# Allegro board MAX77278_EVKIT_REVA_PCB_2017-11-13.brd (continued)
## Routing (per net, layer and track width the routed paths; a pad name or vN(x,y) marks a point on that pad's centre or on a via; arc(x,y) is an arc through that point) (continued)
VBATT: length 3.9
  TOP w0.254: 51.13,39.42 v2(51.21,39.34) 51.08,39.22 C7.2 51,39.19 50.9,39.29 50.9,39.34 v2(50.9,39.34) ; 51.11,39.44 U1.E3
  TOP w0.381: v1(52.6,6.91) 52.62,6.91 ; 52,7.26 v1(52,7.55) C15.1 52.69,7.5 ; v1(52.02,6.99) 52.02,7.1
  INTERNAL2 w0.254: v2(50.9,39.34) 50.95,39.34 51.01,39.29 51.02,39.29 51.05,39.26 51.05,39.2 50.92,39.08 v2(50.9,39.08) 50.91,39.07 50.92,39.07 50.63,39.01 v3(50.58,38.97)
  vias: v2(51.23,39.09) v3(50.39,38.56)
AMUX: length 152.7
  TOP w0.127: v1(20.4,41.63) 20.94,41.63 21.15,41.43 23.34,41.43 23.65,41.73 49.35,41.73 49.63,41.45 U1.C1
  TOP w0.254: v1(83.6,71.05) v1(88.12,71.05)
  INTERNAL3 w0.254: v4(21.4,70.58) 21.4,65.75 20.39,64.73 20.39,42.32 20.4,42.32 v1(20.4,41.63) ; AMUX.1 v4(50.16,70.56) ; J2.2 v4(77.72,71.02)
  BOTTOM w0.254: R285.1 88.21,71.14 v1(88.12,71.05) ; v4(21.4,70.58) 50.04,70.58 ; 50.04,70.58 66.83,70.58 67.09,70.84 76.94,70.84 77.11,71.02 v4(77.72,71.02) 77.97,71.02 78,71.05 v1(83.6,71.05) ; 50.04,70.58 50.05,70.56 v4(50.16,70.56)
BST: length 5.2
  TOP w0.254: C4.1 55.68,38.33 55.68,38.76 v1(55.6,38.84)
  INTERNAL2 w0.254: v2(52.31,41.45) 52.89,41.45 53.04,41.3 v3(53.08,41.3)
  INTERNAL3 w0.254: v3(53.08,41.3) v4(53.55,41.3)
  BOTTOM w0.254: v4(53.55,41.3) 55.17,39.68 55.17,39.27 v1(55.6,38.84)
CHGIN: length 8
  TOP w0.254: U1.E1 49.62,40.65 49.48,40.51 v2(49.43,40.51) ; J1.1 43.59,5.35 43.62,5.38
  TOP w0.381: 43.62,5.38 43.62,8
  TOP w1.27: CHGIN.1 42.76,8.86 43.62,8
  INTERNAL2 w0.254: 49.3,40.08 49.5,40.28 49.5,40.44 v2(49.43,40.51) v2(49.73,40.51) ; 49.27,40.05 49.17,40.05 v3(49.15,40.03)
  vias: v2(48.92,40.34) v2(49.12,40.51) v3(48.72,39.98)
CS: length 57.5
  TOP w0.254: R9.2 52.53,43.48 51.91,42.87 U1.A5
  TOP w0.508: R9.2 53.29,44.46 53.85,45.02 53.85,47.17 v1(54.33,47.65) ; CS.1 v1(58.12,77.6)
  INTERNAL3 w0.508: 58.06,77.77 58.12,77.72 v1(58.12,77.6)
  INTERNAL3 w0.762: v1(54.33,47.65) 58.06,51.38 58.06,94.01 58.04,94.03 J5.2
CTSN: length 20.4
  TOP w0.254: U100.39 22.68,88.62 22.68,88.62 v1(23.34,88.62) ; v1(15.9,80.39) 15.9,79 16.56,78.34 U101.8
  INTERNAL3 w0.254: v1(23.34,80.48) v1(23.34,88.62)
  BOTTOM w0.254: v1(15.9,80.39) 22.64,80.39 22.73,80.48 v1(23.34,80.48)
DCDN: length 7.5
  TOP w0.254: v1(16.64,79.28) 16.64,78.99 17.06,78.57 U101.7 ; v1(17.9,79.28) 18.33,79.71 18.33,79.73 19.53,80.93 U100.25
  BOTTOM w0.254: v1(16.64,79.28) v1(17.9,79.28)
DSRN: length 6.2
  TOP w0.254: U101.6 17.56,78.82 17.33,79.04 17.33,79.44 19.03,81.13 U100.24
DTRN: length 8.2
  TOP w0.254: U101.31 21.87,76.21 v1(22.02,76.35) ; U100.28 21.08,82.82 v1(21.08,81.94)
  INTERNAL3 w0.254: v1(22.02,76.35) 22.02,80.82 21.08,81.76 v1(21.08,81.94)
GPIO0: length 74.2
  TOP w0.127: v1(17.86,43.99) 18.29,43.99 19.08,43.21 49.47,43.21 50.01,42.66 50.01,42.22 50.01,42.21 50.01,41.99 50.15,41.85 U1.B1
  TOP w0.254: R21.2 25.08,63.86 24.93,63.7 GPIO0.1 22.57,63.7 22.54,63.73 v1(19.38,63.73) ; v1(17.86,43.99) 11.38,43.99 8.31,47.07 7.8,47.07 7.8,47.07 SW0.4
  INTERNAL3 w0.152: v1(17.86,43.99) 17.86,57.35 19.33,58.83 19.33,63.12 19.38,63.17 v1(19.38,63.73)
GPIO1: length 58
  TOP w0.127: v1(21.06,59.26) 22.78,59.26 22.81,59.28 23.93,59.28 ; v2(49.74,42.27) 49.71,42.29 49.59,42.29 49.21,42.67 21.31,42.67 v1(21.06,42.42)
  TOP w0.254: 23.93,59.28 GPIO1.1 25.11,59.28 25.16,59.23 R19.2 ; SW1.4 v1(21.08,47.07)
  INTERNAL2 w0.102: v2(50.7,41.88) 50.32,42.27 v2(49.74,42.27)
  INTERNAL3 w0.127: v1(21.06,42.42) v1(21.06,59.26)
  INTERNAL3 w0.254: v1(21.08,47.07) 21.06,47.09
GPIO2: length 71.4
  TOP w0.127: v2(49.71,42.57) 49.34,42.94 19.08,42.94 18.99,42.85 v1(18.44,42.85)
  TOP w0.152: v1(18.44,54.53) 19,54.53 19.02,54.56 22.77,54.56 22.8,54.58 23.93,54.58
  TOP w0.254: SW2.4 7.88,34.78 10.97,37.87 v1(18.44,37.87) ; R16.2 25.16,54.64 25.11,54.58 GPIO2.1 23.93,54.58
  INTERNAL2 w0.102: v2(51.09,41.88) 50.39,42.57 v2(49.71,42.57)
  INTERNAL3 w0.127: v1(18.44,54.53) v1(18.44,42.85)
  INTERNAL3 w0.152: v1(18.44,42.85) v1(18.44,37.87)
GPIO3: length 54.8
  TOP w0.127: v1(22.5,41.83) 23.05,41.83 23.25,42.03 49.49,42.03 v2(49.79,41.74)
  TOP w0.152: v1(22.1,34.9) 21.54,34.9 21.42,34.78 SW3.4
  TOP w0.254: 25.29,50.06 26.47,50.06 26.52,50.11 ; 25.29,50.06 GPIO3.1 ; 25.29,50.06 25.34,50.11 26.52,50.11 ; 26.52,50.11 R6.2
  INTERNAL2 w0.102: v2(49.79,41.74) 50.09,41.43 50.22,41.43 50.22,41.43 v2(50.69,41.43)
  INTERNAL3 w0.152: 24.1,50.06 22.5,48.46 v1(22.5,41.83) 22.5,41.27 22.1,40.87 v1(22.1,34.9)
  INTERNAL3 w0.254: GPIO3.1 24.1,50.06
GPIO4: length 69.8
  TOP w0.127: SW4.4 7.81,22.84 7.84,22.86 8.1,22.86 11.51,26.26 v1(20.5,26.26) ; v1(45.77,41.15) 25.06,41.15 24.78,40.87 v1(24.23,40.87) 23.69,40.87 23.51,41.05 21.22,41.05 21.04,40.87 v1(20.5,40.87)
  TOP w0.254: R8.1 25.44,45.42 25.39,45.36 GPIO4.1
  INTERNAL2 w0.102: v2(51.51,41.05) 51.05,40.59 51.03,40.59 v3(50.67,40.23)
  INTERNAL3 w0.102: v3(50.67,40.23) 50.67,40.87 49.82,41.72 46.34,41.72 v1(45.77,41.15)
  INTERNAL3 w0.127: v1(20.5,40.87) v1(20.5,26.26)
  INTERNAL3 w0.254: GPIO4.1 24.51,43.92 24.23,43.64 v1(24.23,40.87)
GPIO5: length 60.2
  TOP w0.127: 24.49,37.64 v1(21.51,37.64) ; v2(49.12,42.34) 22.42,42.34 22.21,42.14 v1(21.67,42.14)
  TOP w0.152: v1(21.51,22.86) 20.96,22.86 20.93,22.84 SW5.4
  TOP w0.381: 24.49,37.64 GPIO5.1 25.73,37.64 25.76,37.67 R18.1
  INTERNAL2 w0.076: v2(51.11,41.45) 51.1,41.45 50.9,41.66 50.5,41.66
  INTERNAL2 w0.127: v2(49.12,42.34) 49.42,42.05 49.6,42.05 49.66,41.99 49.99,41.99 50.32,41.66 50.5,41.66
  INTERNAL3 w0.127: v1(21.51,22.86) v1(21.51,37.64) 21.51,41.44 21.67,41.59 v1(21.67,42.14)
GPIO6: length 86.1
  TOP w0.127: v2(49.96,43.1) 49.59,43.47 19.91,43.47 19.65,43.74 v1(19.1,43.74)
  TOP w0.152: v1(18.92,13.34) 9.17,13.34 7,11.16 SW6.4 ; 24.41,33.05 v1(19.1,33.05)
  TOP w0.381: R20.1 25.68,33.02 25.65,33.05 GPIO6.1 24.41,33.05
  INTERNAL2 w0.076: v2(51.49,41.48) 51.49,41.53 51.31,41.71 51.31,42.01 50.98,42.34
  INTERNAL2 w0.102: 50.98,42.34 50.5,42.82 50.25,42.82 v2(49.96,43.1)
  INTERNAL3 w0.127: v1(19.1,43.74) v1(19.1,33.05)
  INTERNAL3 w0.152: v1(18.92,13.34) 18.92,32.31 19.1,32.49 v1(19.1,33.05)
GPIO7: length 97.1
  TOP w0.152: 24.41,27.76 23.28,27.76 23.25,27.79 v1(19.74,27.79) ; SW7.4 v1(19.73,10.09)
  TOP w0.381: R22.1 25.81,27.91 25.65,27.76 GPIO7.1 24.41,27.76
  INTERNAL2 w0.076: v2(51.54,41.88) 51.85,42.19 51.85,42.63
  INTERNAL2 w0.102: v3(51.92,43.21) 51.92,42.7 51.85,42.63
  INTERNAL3 w0.127: v3(51.92,43.21) 51.92,44.22 51.13,45.01 51.13,52.86 v1(50.95,53.04)
  INTERNAL3 w0.152: v1(19.73,10.09) 19.73,10.13 19.74,10.13 v1(19.74,27.79) 19.74,44.73 19.61,44.86 v1(19.61,53.04)
  BOTTOM w0.152: v1(50.95,53.04) v1(19.61,53.04)
GROUND: length 133.9
  TOP w0.152: v1(83.05,8.62) 82.8,8.37 U206.A3 ; C224.2 v1(83.83,6.29)
  TOP w0.203: U1.E4 51.51,40.39 v2(51.51,40.39)
  TOP w0.254: C159.2 21.23,78.91 v1(20.88,78.56) ; C158.1 v1(33.14,90.21) 33.15,90.22 33.46,89.9 R159.2 ; v1(18.36,81.92) 18.36,81.72 C150.2 18.09,81.43 18.53,81.87 U100.23 ; R166.2 v1(55.52,82.27) ; U101.26 21.56,73.71 v1(21.69,73.58) ; U103.2 38.21,86.19 38.44,85.96 C110.1 v1(39.31,85.2) ; Y101.4 v1(27.95,94.12) ; U100.1 12.88,90.12 v1(12.34,90.65) ; v1(28.22,76.94) 28.56,77.28 U107.5 U107.13 ; Q100.2 36.09,45.67 R138.2 ; 44.86,85.67 45.08,85.45 C112.1 ; C15.2 54.09,7.55 54.38,7.85 v1(54.86,7.85) ; U101.20 18.06,71.67 v1(17.83,71.45) ; 9.5,70.1 9.26,69.87 R115.2 ; 9.5,70.1 C154.1 ; 9.5,70.1 9.9,70.1 9.9,70.19 v1(9.99,70.28) ; U100.35 23.69,86.62 v1(23.95,86.36) ; U100.3 12.79,89.12 v1(12.42,88.75) 12.55,88.62 U100.4 ; U1.E6 52.31,40.37 ; R157.2 45.33,90.38 C113.1 ; v1(27.03,84.8) C120.1 27.04,84.2 27.85,84.2 27.86,84.21 C115.1 ; v1(33.32,85.26) 32.73,85.26 C118.1 32.51,85.13 32.51,85.51 32.27,85.75 U102.2 ; U101.17 16.44,72.33 v1(15.56,72.33) 15.51,72.28 C156.1 14.35,72.3 C155.2 ; R13.2 v1(24.86,7.13) ; v1(18.06,78.56) 18.56,78.06 U101.4 ; Y101.2 23.7,91.92 C152.1 23.55,91.02 v1(23.93,90.64) 24.22,90.35 C153.1 ; C6.1 54.81,40.11 54.81,39.73 ; C134.1 41.63,48.29 v1(41.49,48.15) 41.37,48.02 Q101.2 40.68,47.11 40.79,47.01 R137.2 ; U101.24 20.19,72.33 v1(20.46,72.33) ; R161.2 39.76,89.99 v1(39.32,90.42) 39.27,90.38 C111.1 ; v1(64.11,83.2) 63.55,83.76 R7.2 62.84,83.84 Q1.2 ; U104.2 44.79,85.83 ; v1(26.52,89.28) 26.42,89.18 26.16,89.18 25.87,88.89 C151.2 ; RT1.2 v1(29.26,6.05) ; v2(51.51,42.25) 51.51,43.23 ; C108.1 v1(15.63,70.73) ; v1(37.11,47.19) 37.06,47.24 C129.1
  TOP w0.381: C5.1 54.81,43.36 54.81,43.29 ; C5.1 54.91,43.44 55,43.53 v1(55.26,43.53) ; C5.1 55.29,43.84 C36.1 55.52,44.48 C37.1 ; Q100.2 36.84,46.93 v1(37.11,47.19) ; U108.2 49.6,81.41 v1(48.46,81.41) ; C12.1 48.37,43.94 v1(47.79,43.94) ; C241.1 89.37,33.56 ; 31.25,91.85 31.2,91.9 v1(30.66,91.9) ; J6.5 5.49,75.82 5.49,75.82 6.89,75.82 6.9,75.82 v1(7.57,75.82) ; C242.1 89.84,62.02 ; C113.1 44.58,90.01 v1(44.78,89.81) ; C239.1 v1(90.04,49.28) ; v2(54.98,41.68) 54.89,41.77 C9.1 54.88,41.82 C8.1 ; v1(27.54,89.89) R110.2
  TOP w0.457: v1(41.05,6.81) 41.05,5.34 J1.5
  TOP w0.508: R23.2 v1(21.87,19.58) ; SW9.3 v1(1.2,57.88)
  INTERNAL2 w0.254: v2(51.51,40.39) 50.88,39.75 50.35,39.75
  BOTTOM w0.127: R233.2 90.16,42.33 90.08,42.42 89.5,42.42 88.38,41.29 84.87,41.29 84.13,42.03 R230.2 ; 90.43,34.98 90.43,35.39 90.3,35.51 89.87,35.51 88.39,34.04 85.09,34.04 84.61,34.52 83.72,34.52 R243.2 ; R255.2 88.3,62.7 89.08,63.47 89.99,63.47 90.03,63.43 90.05,63.43 R258.2 ; R211.2 90.18,50.62 90.11,50.69 89.47,50.69 87.92,49.14 R208.2
  BOTTOM w0.254: U209.15 88.95,82.26 89.56,82.87 R282.2 89.56,83.93 ; C222.1 v1(64.45,73.42) ; v1(92.86,54.25) 92.86,53.95 R210.1 ; 89.56,83.93 C238.1 ; 89.56,83.93 89.63,83.86 C237.1 v1(91.45,83.86) ; C249.1 v4(89.54,72.82) ; v1(62.74,79.96) R308.1 63.48,79.93 R307.1 ; U205.4 68.65,73.48 68.31,73.13 v1(68.31,72.83) ; v4(83.63,71.97) 84.25,71.97 C228.1 ; C223.1 v1(71.24,71.97) ; R257.1 v1(96.01,67.03)
  BOTTOM w0.381: C251.1 65.63,65.56 65.67,65.59 65.67,65.92 v1(65.68,65.94) ; v1(99.72,73.61) 99.65,73.54 99.24,73.54 U210.2 ; R211.2 90.04,49.88 v1(90.04,49.28) ; C244.1 90.92,76.59 v1(90.95,76.62) ; U207.2 85.26,13.46 85.56,13.75 R268.2 86.78,13.75 C227.2 86.8,14.83 C236.1 v1(86.99,15.64) ; 98.13,38.85 97.76,38.48 R244.1 ; C226.2 v1(81.85,16.14) ; R287.2 98.81,78.91 98.81,78.24 v1(98.75,78.18) ; R231.1 96.03,42.55 v1(96.07,42.51) ; C235.1 93.52,73.57 C234.1 92.78,73.56 v1(92.33,74.02) ; v1(66.27,29.84) 66.26,29.84
  BOTTOM w0.508: Q206.2 v1(98.75,78.18)
  vias: v1(7.29,65.3) v1(7.98,82.91) v1(9.8,69.6) v1(10.29,77.47) v1(12.55,94.18) v1(13.36,1.83) v1(18.34,1.93) v1(19.18,48.06) v1(20.32,25.6) v1(21.29,94.59) v1(31.45,1.93) v1(32.97,9.02) v1(32.97,8.46) v1(33.49,9) v1(33.53,8.46) v1(40.34,7.52) v1(40.34,6.81) v1(41.05,7.52) v1(43.28,60.11) v1(43.28,59.51) v1(43.28,58.89) v1(43.34,56.76) v1(43.34,56.16) v1(43.37,55.52) v1(43.9,60.14) v1(43.9,59.49) v1(43.88,58.89) v1(43.95,56.78) v1(43.96,56.14) v1(43.94,55.54) v1(44.04,49.81) v1(44.07,49.17) v1(45.69,35.37) v1(45.71,34.73) v1(46.29,35.36) v1(46.29,34.72) v1(48.21,89.18) v1(49.15,46.53) v1(49.8,37.21) v1(50.29,46) v1(50.39,37.22) v1(51.36,2.24) v1(54.86,7.32) v1(55.52,7.85) v1(55.52,7.32) v1(55.73,44.04) v1(57.35,2.24) v1(59.22,14.31) v1(59.22,13.67) v1(61.74,8.16) v1(62.97,8.16) v1(63.4,42.11) v1(65.63,49.94) v1(65.61,40.64) v1(66.23,14.79) v1(66.18,8.27) v1(66.28,13.67) v1(67.46,14.79) v1(67.41,8.27) v1(67.53,13.68) v1(68.5,66.52) v1(68.5,50.47) v1(69.29,40.74) v1(69.44,2.24) v1(69.67,13.56) v1(69.66,11.87) v1(69.75,34.44) v1(69.93,29.03) v1(69.95,26.39) v1(70.05,50.8) v1(70.05,49.68) v1(70.79,13.55) v1(70.97,68.88) v1(70.89,11.87) v1(72.29,72.9) v1(73.08,44.4) v1(73.27,43.22) v1(73.24,41.89) v1(73.56,34.54) v1(73.66,60.55) v1(73.74,26.44) v1(74.22,75.59) v1(74.48,41.89) v1(74.5,43.22) v1(74.9,71.32) v1(75.13,82.07) v1(75.64,41.66) v1(76.15,41.05) v1(76.45,61.57) v1(76.45,60.86) v1(76.66,40.64) v1(76.66,33.17) v1(76.81,57.78) v1(76.8,57.21) v1(76.96,2.13) v1(77.27,60.86) v1(78.03,57.78) v1(78.03,57.21) v1(78.69,61.47) v1(78.82,33.5) v1(79.3,41.15) v1(79.5,61.47) v1(79.58,33.5) v1(79.71,49.28) v1(79.81,41.66) v1(79.96,35.69) v1(79.96,34.87) v1(79.96,34.11) v1(80.01,62.69) v1(80.01,61.98) v1(80.11,50.5) v1(80.11,49.78) v1(80.11,42.27) v1(81.27,74.24) v1(81.24,3.13) v1(81.24,2.57) v1(81.53,79.76) v1(82.02,3.13) v1(82.03,2.58) v1(84.07,84.18) v1(84.2,81.73) v1(85.5,70.41) v1(85.5,68.17) v1(86.31,61.26) v1(86.41,57.71) v1(86.41,53.75) v1(86.49,40.51) v1(86.74,19) v1(88.62,18.82) v1(88.86,20.84) v1(89.92,62.1) v1(90.1,20.84) v1(90.09,18.14) v1(90.55,9.55) v1(90.68,49.28) v1(90.8,63.12) v1(90.8,62.48) v1(90.8,49.91) v1(90.8,42.24) v1(90.8,41.63) v1(91.06,35.05) v1(91.06,34.42) v1(91.49,54.05) v1(91.9,67.16) v1(92.66,9.47) v1(97.69,58.72) v1(98.17,38.89) v1(98.58,76.48) v1(98.81,47.96) v1(98.81,38.91) v2(47.36,40.55) v2(47.35,40.25) v2(47.36,39.94) v2(47.66,40.24) v2(47.71,41.27) v2(47.68,40.54) v2(49.76,38.11) v2(49.75,37.8) v2(50.04,38.09) v2(50.04,37.81) v2(50.31,38.1) v2(50.32,37.8) v2(50.84,38.37) v2(50.84,38.07) v2(51.16,38.39) v2(51.16,38.09) v2(51.16,37.8) v2(51.47,38.39) v2(51.47,38.09) v2(53.88,39.66) v2(53.88,39.33) v2(53.87,39.03) v2(54.19,39.68) v2(54.2,39.33) v2(54.21,39.03) v2(54.5,39.68) v2(54.5,39.34) v2(54.81,39.69) v2(54.83,39.34) v2(54.98,41.96) v2(54.91,41.13) v2(54.91,40.79) v2(55.16,41.1) v2(55.16,40.77) v2(55.16,40.39) v2(55.16,40.06) v2(55.47,41.09) v2(55.47,40.77) v2(55.5,40.4) v2(55.51,40.06) v2(82.36,7.97)
IBATT: length 3.6
  BOTTOM w0.254: C228.2 85.14,71.98 R269.2 85.36,72.81 85.77,73.23 U209.7
IBATT_SNS: length 3.3
  TOP w0.127: U206.C1 81.92,7.53 v1(81.38,7.53)
  BOTTOM w0.127: R261.1 79.47,8.01 79.56,7.92 80.99,7.92 v1(81.38,7.53)
IBATT_SNS_RNG: length 135.2
  TOP w0.152: U206.A2 82.36,9.34 82.45,9.44 R284.2 v1(84.56,10.02)
  INTERNAL3 w0.152: v4(42.98,88.49) 42.98,90.5 40.56,92.91 J100.5 ; v1(84.56,5.52) v1(84.56,10.02) 84.56,11.14 81.37,14.34 81.37,72.86 81.91,73.41 v1(81.91,88.49)
  BOTTOM w0.152: v1(81.91,88.49) v4(42.98,88.49)
  BOTTOM w0.254: v1(84.56,5.52) 84.49,5.44 Q204.1
IN_SBB: length 6.1
  TOP w0.254: v1(61.09,13.94) 60.75,13.94 60.67,13.86 ; v2(52.14,39.32) 52.11,39.32 51.98,39.45 52.04,39.47 v2(52.13,39.63) ; v2(52.14,39.32) 52.14,39.32 52.1,39.32 51.91,39.48 51.88,39.48 ; v2(52.14,39.32) 52.14,39.33 52.12,39.33 ; C1.2 51.91,39.42 U1.E5
  INTERNAL2 w0.254: 52.11,39.35 52.06,39.31 v2(51.89,39.13) ; v2(52.14,39.32) 52.14,39.35 52.1,39.41 v2(52.13,39.63) ; v3(51.52,39.7) 51.56,39.69 51.57,39.66 51.57,39.43 51.87,39.13 v2(51.89,39.13) ; v2(51.89,39.13) 51.89,39.37 51.88,39.48
  INTERNAL3 w0.254: v4(51.92,39.39) 51.61,39.7 v3(51.52,39.7) 51.64,39.77 v3(51.82,40.01)
  BOTTOM w0.254: v4(51.92,39.39) 51.94,39.42 52.49,39.42 v4(52.47,39.39)
  vias: v1(60.73,12.83) v1(61.93,13.92) v1(61.9,12.83) v1(62.79,13.92) v1(62.81,12.83) v2(51.88,39.52)
INLDO: length 5.5
  TOP w0.254: 53.63,42.45 53.3,42.11 53.3,42.01 53.09,41.81 52.76,41.81 U1.B7
  TOP w0.381: R11.1 55.91,42.62 v1(56.22,42.93) ; 79.81,53.72 79.8,53.73 C18.2 ; 53.63,42.45 53.8,42.45 C13.1
  TOP w1.27: 83.32,53.69 INLDO.1
  INTERNAL2 w0.381: v2(53.89,42.64) 53.89,42.63 v3(54.23,42.63)
  INTERNAL3 w0.508: v1(56.22,42.93) 55.92,42.63 v3(54.23,42.63)
ISET_LDO: length 11.7
  INTERNAL3 w0.254: v1(64.49,72.67) v1(64.49,66.24)
  BOTTOM w0.254: v1(64.49,72.67) 66.37,72.67 67.35,73.65 U205.6 ; R250.1 64.49,65.54 v1(64.49,66.24)
ISET_SBB0: length 30.8
  INTERNAL3 w0.254: v4(64.71,49.98) 64.71,52.13 64.69,52.15 v4(64.69,52.89) ; v4(69.95,73.29) v4(69.95,52.89)
  BOTTOM w0.254: U205.2 v4(69.95,73.29) ; v4(69.95,52.89) v4(64.69,52.89) ; R203.1 v4(64.71,49.98)
ISET_SBB1: length 40.6
  INTERNAL3 w0.254: v4(64.74,42.55) v4(64.74,39.45) ; v4(69.3,72.55) v4(69.3,42.55)
  BOTTOM w0.254: v4(69.3,42.55) v4(64.74,42.55) ; v4(64.74,39.45) 64.74,38.83 R224.1 ; U205.3 v4(69.3,72.55)
ISET_SBB2: length 47
  INTERNAL3 w0.254: v4(67.57,73.11) v4(67.57,31.22)
  BOTTOM w0.254: v4(67.57,73.11) 68,73.54 U205.5 ; R237.1 64.63,30.72 65.13,31.22 v4(67.57,31.22)
LDO: length 3.7
  TOP w0.254: C5.2 53.9,43.44 53.24,42.77 53.13,42.77 52.71,42.35 U1.A7
  TOP w0.381: C37.2 54.39,44.81 C36.2 53.99,43.85 C5.2
  vias: v2(53.91,43.45)
LDO_DIV: length 13.8
  BOTTOM w0.254: U204.6 U204.7 76.14,79.02 76.35,78.82 86.06,78.82 86.39,79.15 86.39,79.41 86.41,79.43 U209.11
LXA: length 3.7
  TOP w0.254: v2(52.14,38.07) 52.17,38.09 52.29,38.09 ; v2(52.14,38.36) 52.29,38.21 52.29,38.09 ; 52.29,38.09 52.32,38.06 v2(52.42,38.06) ; 52.29,38.09 52.43,38.24 v2(52.43,38.36)
  INTERNAL2 w0.254: v2(51.91,41.05) 51.94,41.02 51.94,40.75 52.28,40.41
  INTERNAL2 w0.508: 52.66,38.6 52.66,40.03 52.28,40.41
LXB: length 3.8
  TOP w0.254: v2(53.43,38.05) 53.48,38.09 53.71,38.09 v2(53.76,38.04) ; v2(53.76,38.38) 53.63,38.25 53.63,38.18 v2(53.43,38.38)
  INTERNAL2 w0.254: v2(52.31,41.05) 52.52,41.05 52.88,40.69
  INTERNAL2 w0.508: 53.31,38.7 53.31,40.26 52.88,40.69
MAXQP03: length 1.8
  TOP w0.254: PO3.1 16.39,91.96 16.53,91.82 U100.52
MAXQP05: length 2
  TOP w0.254: PO5.1 14.89,92.05 15.53,91.4 U100.54
NEN: length 131.9
  TOP w0.127: v1(52.34,84.81) v1(80.26,84.81)
  INTERNAL2 w0.076: v2(51.92,41.45) 51.94,41.45 52.12,41.63 52.12,41.96 52.34,42.18
  INTERNAL2 w0.127: v3(52.4,42.32) 52.34,42.25 52.34,42.18
  INTERNAL3 w0.127: v1(52.34,84.81) v4(52.34,62.18) 52.93,61.58 52.93,44.58 52.77,44.41 52.77,42.68 v3(52.4,42.32) ; v1(80.26,84.81) J2.3
  INTERNAL3 w0.254: v4(40.72,62.18) 40.72,75.67 NEN.1
  BOTTOM w0.152: 18.27,62.15 18.3,62.18 v4(40.72,62.18) v4(52.34,62.18)
  BOTTOM w0.254: J8.2 18.17,62.26 18.27,62.15
NIRQ: length 122.4
  TOP w0.127: v1(82.8,77.06) 62.97,77.06 v1(61.52,75.62)
  TOP w0.152: v1(61.32,69.57) 60.76,69.57 60.66,69.67 v1(51.51,69.67) ; v1(24.64,76.81) 24.66,76.79 R14.1
  TOP w0.254: R150.2 24,77.46 v1(24.64,76.81)
  INTERNAL2 w0.076: v2(51.89,41.83) 51.89,41.99 52.07,42.16 52.07,42.57
  INTERNAL2 w0.102: v3(52.31,42.82) 52.31,42.81 52.07,42.57
  INTERNAL3 w0.127: J2.4 v1(82.8,77.06) ; v3(52.31,42.82) 52.31,44.49 51.49,45.31 51.49,68.58 51.51,68.61 v1(51.51,69.67)
  INTERNAL3 w0.152: v1(61.52,75.62) 61.52,74.18 61.39,74.05 NIRQ.1 61.39,71.79 61.32,71.72 v1(61.32,69.57)
  BOTTOM w0.152: v1(24.64,76.81) 25.38,76.07 60.5,76.07 60.96,75.62 v1(61.52,75.62)
NIRQ1: length 27
  TOP w0.254: R152.1 v1(33.11,81.68) ; U100.49 18.03,91.7 18.59,92.26 18.59,93.38 PO0.1
  INTERNAL3 w0.254: v1(33.11,81.68) 33.11,84.18 31.75,85.55 31.75,89.23 v1(30.18,90.81)
  BOTTOM w0.254: PO0.1 21.91,93.53 22.63,92.81 28.19,92.81 29.74,91.26 29.74,91.24 v1(30.18,90.81)
NRST: length 84.6
  TOP w0.127: 55.85,73.03 57.61,74.78 61.93,74.78 63.65,76.5 v1(83.54,76.5)
  TOP w0.152: NRST.1 55.85,73.03
  TOP w0.254: 55.85,73.03 54.35,74.53 R10.1 53.04,73.89 v1(53.06,73.86)
  INTERNAL2 w0.127: v3(52.96,41.94) 52.85,41.83 v2(52.34,41.83)
  INTERNAL3 w0.127: 53.67,63.14 53.59,63.07 53.59,42.57 v3(52.96,41.94) ; J2.5 85.34,92.33 83.54,90.53 v1(83.54,76.5)
  INTERNAL3 w0.152: v1(53.06,73.86) 53.67,73.25 53.67,63.14
P01: length 146.3
  TOP w0.152: R284.1 81.6,10.02 81.55,10.07 v1(75.9,10.07)
  TOP w0.254: U100.50 17.53,92.38 PO1.1 ; v1(31.04,18.54) 74.02,18.54 74.04,18.52 v1(75.9,18.52)
  INTERNAL3 w0.254: v1(75.9,18.52) v1(75.9,10.07) ; v1(31.04,18.54) 31.04,19.15 30.98,19.21 30.98,88.56 30.89,88.66 v4(30.89,89.27)
  BOTTOM w0.254: v4(30.89,89.27) 27.9,92.25 22.19,92.25 21.78,92.66 PO1.1
P02: length 2.6
  TOP w0.254: U100.51 17.03,92.8 17.02,92.81 PO2.1
P04: length 2.8
  TOP w0.254: U100.53 16.03,91.77 15.62,92.18 15.62,92.67 15.5,92.79 PO4.1
P06: length 3
  TOP w0.254: PO6.1 14.2,92.78 14.17,92.75 14.17,92.08 15.03,91.22 U100.55
P07: length 2.2
  TOP w0.254: U100.56 14.53,91.17 13.52,92.18 PO7.1
REF_1: length 76
  INTERNAL3 w0.254: v1(94.54,13.77) 94.54,56.79 95.05,57.3 95.05,70.15 93.07,72.14 v1(93.07,76.3)
  BOTTOM w0.254: U209.1 90.28,75.08 90.28,75.08 C244.2 90.94,75.06 91.74,75.06 92.27,75.58 R279.2
  BOTTOM w0.381: C236.2 R265.1 93.24,13.71 93.3,13.77 v1(94.54,13.77) ; R279.2 93.05,76.29 v1(93.07,76.3)
RIN: length 6
  TOP w0.254: U101.3 19.06,79.82 20.52,81.28 20.52,81.96 20.53,81.97 U100.27
RTSN: length 7.3
  TOP w0.254: U101.32 21.26,76.71 v1(21.34,76.78) ; U100.26 20.04,82.86 v1(20.04,81.61)
  INTERNAL3 w0.254: v1(20.04,81.61) 21.44,80.21 21.44,77.5 21.34,77.39 v1(21.34,76.78)
RXD: length 15.3
  TOP w0.254: U100.43 21.56,90.87 v1(21.74,91.05) ; v1(21.74,81.84) 19.56,79.66 U101.2
  INTERNAL3 w0.254: v1(21.74,81.84) v1(21.74,91.05)
SBB0: length 6.6
  TOP w0.254: C9.2 53.96,41.8 53.61,41.8 53.26,41.45 U1.C7
  TOP w0.381: R11.2 56.79,41.72 v1(56.8,41.73)
  TOP w0.508: v1(56.8,41.73) 57.54,41.73 57.91,42.11
  INTERNAL2 w0.254: 54.37,41.64 v3(54.42,41.7) 54.33,41.7 ; 54.11,41.85 v2(54,41.95) ; v2(53.98,41.66) 54.01,41.64
  INTERNAL3 w0.508: v3(54.42,41.7) 55.52,41.7 55.53,41.71 56.04,41.71 56.06,41.73 v1(56.8,41.73)
SBB0_DIV: length 9.2
  BOTTOM w0.381: U204.2 U204.1 84.08,75.5 84.49,75.08 U209.8
SBB1: length 60.8
  TOP w0.254: C8.2 53.96,40.94 53.91,40.94 53.8,41.05 U1.D7
  TOP w0.508: 58.29,40.89 v1(56.26,40.89)
  TOP w1.27: 61.09,40.89 58.29,40.89 ; J203.2 90.63,38.93
  INTERNAL2 w0.254: 54.21,41.03 v3(54.35,40.89) 54.3,40.83 ; v2(54.08,40.86) 54.1,40.83 ; v2(53.87,41.05) 53.9,41.03
  INTERNAL3 w0.254: v1(61.06,40.84) 61.06,63.7 63.4,66.04 63.4,89.69 J101.6
  INTERNAL3 w0.508: v3(54.35,40.89) v1(56.26,40.89)
SBB2: length 5.2
  TOP w0.254: 53.96,40.21 C6.2 ; U1.E7 53.07,40.29 53.29,40.29
  TOP w0.508: 58.04,39.12 57.01,40.15 v1(56.98,40.15)
  TOP w1.27: 83.19,31.54 SBB2.1
  INTERNAL2 w0.254: 54.46,40.13 v3(54.48,40.15) 54.3,40.33 ; v2(53.87,40.28) 53.92,40.33 ; v2(54.08,40.08) 54.13,40.13
  INTERNAL3 w0.508: v3(54.48,40.15) v1(56.98,40.15)
SCL: length 129.8
  TOP w0.127: U1.A3 51.11,42.7 50.93,42.88 50.93,43.61 49.53,45.01 ; v1(87.88,90.12) 60.15,90.12 v1(59.56,89.53)
  TOP w0.152: v1(42.55,49.86) 41.7,49.86 C134.2 ; v1(42.62,45.39) 49.15,45.39 49.53,45.01
  TOP w0.254: R107.2 23.99,79.82 R136.2 v1(23.33,79.82) ; Q101.3 40.89,49.82 41,49.93 C134.2
  INTERNAL3 w0.127: J2.6 v1(87.88,90.12) ; v1(59.56,89.53) v1(59.56,79.38)
  INTERNAL3 w0.152: v1(23.33,79.82) 23.33,77.8 23.34,77.79 v4(23.34,77.52) ; SCL.1 42.55,75.95 v1(42.55,49.86) 42.55,46.02 42.62,45.95 v1(42.62,45.39)
  BOTTOM w0.152: v4(23.34,77.52) 24.61,77.52 25.68,76.45 43.05,76.45 SCL.1 47.88,77.52 49.73,79.38 v1(59.56,79.38)
SCL1: length 101.2
  TOP w0.254: R155.2 v1(26.24,86.85) 26.66,86.85 R118.1 ; U107.9 30.46,81.26 30.3,81.42 v1(30.3,82.91) 37.8,82.91 39.04,81.66 46.31,81.66 46.49,81.84 R162.1
  INTERNAL3 w0.152: J100.3 35.48,92.84 34.28,91.63 v4(34.28,87.11)
  INTERNAL3 w0.203: v1(65.85,82.44) v1(65.85,86.66)
  INTERNAL3 w0.254: v1(26.24,86.85) 27.34,86.85 28.76,85.44 28.76,83.84 29.69,82.91 v1(30.3,82.91)
  BOTTOM w0.152: 34.19,87.12 51.92,87.12 52.37,86.67 67.99,86.67 68.15,86.51 84.91,86.51 85.4,87 R304.1 ; 34.19,87.12 34.2,87.11 v4(34.28,87.11) ; 34.19,87.12 27.06,87.12 26.8,86.85 v1(26.24,86.85)
  BOTTOM w0.203: R305.1 66.85,82.44 v1(65.85,82.44) ; v1(65.85,86.66) 65.62,86.66 65.61,86.67
SDA: length 139.5
  TOP w0.127: U1.A2 50.71,42.7 50.69,42.72 50.69,43.4 49.12,44.96 38.47,44.96 38.39,44.88 v1(37.85,44.88)
  TOP w0.152: v1(37.85,48.77) 37.07,48.77 C129.2 ; SDA.1 47.57,79.98 39.48,79.98 v1(37.42,82.04) ; v1(60.33,89.05) 60.71,89.43 v1(90.42,89.43)
  TOP w0.254: C129.2 36.2,48.76 36.17,48.73 Q100.3 ; R135.2 24.01,81.31 R108.2 v1(24.02,82.03)
  INTERNAL3 w0.152: J2.7 v1(90.42,89.43) ; v1(37.85,44.88) v1(37.85,48.77) 37.85,71.02 37.39,71.48 37.39,80.98 37.42,81.01 v1(37.42,82.04) ; v1(60.33,89.05) v1(60.33,78.71)
  BOTTOM w0.152: SDA.1 51.23,78.71 v1(60.33,78.71) ; v1(37.42,82.04) 36.86,82.04 36.82,82.08 32.94,82.08 32.89,82.03 v1(24.02,82.03)
SDA1: length 100.9
  TOP w0.254: U107.10 v1(29.36,84.2) 30.07,83.49 38.02,83.49 39.13,82.38 v1(45.71,82.38) ; R100.1 26.64,87.67 v1(26.24,87.67) R148.2 ; R164.2 v1(45.69,80.54)
  INTERNAL3 w0.152: J100.4 v4(38.02,87.83)
  INTERNAL3 w0.203: v1(66.53,83.3) v1(66.53,87.16)
  INTERNAL3 w0.254: v1(26.24,87.67) 27.44,87.67 29.36,85.75 v1(29.36,84.2) ; v1(45.71,82.38) 45.71,81.17 45.69,81.15 v1(45.69,80.54)
  BOTTOM w0.152: 38.3,87.85 38.29,87.83 v4(38.02,87.83) ; 38.3,87.85 26.98,87.85 26.8,87.67 v1(26.24,87.67) ; 38.3,87.85 51.8,87.85 52.48,87.17 84.89,87.17 85.7,87.99 R303.1
  BOTTOM w0.203: 66.37,87.17 66.38,87.16 v1(66.53,87.16) ; R306.1 67.16,83.46 67,83.3 v1(66.53,83.3)
THM: length 62.9
  TOP w0.254: v1(22.71,39.37) 23.32,39.37 23.72,39.78 v1(46.28,39.78) ; THM.1 22.73,22.5 v1(22.71,22.48)
  INTERNAL2 w0.152: v2(50.71,41.05) 49.93,41.05 49.92,41.06 v3(49.77,41.06)
  INTERNAL3 w0.152: v1(46.28,39.78) 46.67,40.17 46.78,40.17 47.4,40.79 48.98,40.79 49.24,41.06 v3(49.77,41.06)
  INTERNAL3 w0.254: v1(22.71,39.37) v1(22.71,22.48) 22.71,15.37 22.5,15.16 v4(22.5,14.43)
  BOTTOM w0.254: J3.5 J3.3 J3.1 v4(22.5,14.43)
THMB: length 71.4
  TOP w0.254: 29.29,5.54 28.68,5.54 28.06,6.15 ; 29.29,5.54 v1(32.33,5.54) ; 29.29,5.54 29.29,5.53 R12.1 ; 28.06,6.15 R1.1 28.05,7.13 R15.1 ; 28.06,6.15 28.06,6.14 27.71,5.79 20.5,5.79 TBIAS.1 ; v1(32.51,38.86) 45.64,38.86 45.66,38.85 v1(46.27,38.85)
  INTERNAL2 w0.152: v2(51.11,41.05) 50.82,40.77 50.49,40.77 50.37,40.65 v3(50.27,40.65)
  INTERNAL3 w0.152: v3(50.27,40.65) 49.74,40.65 49.56,40.47 47.89,40.47 v1(46.27,38.85)
  INTERNAL3 w0.254: v1(32.51,38.86) 32.51,12.8 32.33,12.62 v1(32.33,5.54)
TXD: length 20.8
  TOP w0.254: v1(22.64,75.58) 21.82,75.58 21.69,75.71 U101.30 ; v1(21.54,91.85) 20.78,91.85 20.53,91.59 U100.44
  INTERNAL3 w0.254: v1(21.54,91.85) 22.15,91.85 22.64,91.35 v1(22.64,75.58)
UNNAMED_1_10103592-0001LF_I172_SHIELD10: length 21.9
  TOP w0.457: 39.89,5.53 39.87,5.51 J1.7 ; J1.10 43.23,2.18 43.15,2.25 ; J1.8 44.72,5.51 44.74,5.53 ; 41.38,2.25 41.35,2.23 J1.11 ; 38.22,2.45 38.19,2.43 J1.6 ; J1.9 46.33,2.36
  TOP w0.762: 44.74,5.53 44.74,4.13 46.42,2.45 46.22,2.25 41.38,2.25 41.18,2.45 38.22,2.45 39.89,4.13 39.89,5.53 37.47,5.53 37.44,5.56 R3.1 35.75,5.58 35.75,6.74 R4.1
UNNAMED_1_CAPNP_I179_2: length 1.1
  TOP w0.508: DS2.3 DS2.2
UNNAMED_1_CL-SB-12B-1X_I99_2: length 13.4
  TOP w0.254: J8.3 17.68,64.8 14.73,61.85 6.74,61.85 6.68,61.8 SW9.2
UNNAMED_1_EKCAPNP_I55_1: length 1.3
  TOP w0.762: C10.1 34.39,6.74 34.39,5.61 R3.2
UNNAMED_1_EKCAPNP_I69_2: length 36.7
  TOP w0.152: U1.A1 50.31,42.72
  TOP w0.254: v1(46.38,44.55) 48.9,44.55 49.33,44.12 C12.2 49.38,43.84 49.76,43.84 50.31,43.28 50.31,42.72 ; v1(46.3,74.6) 46.35,74.56 R17.1
  INTERNAL3 w0.254: v1(46.3,74.6) 46.3,45.24 46.38,45.16 v1(46.38,44.55)
UNNAMED_1_EKMAX77278_I115_CSEN: length 95.9
  TOP w0.127: v2(52.65,43.05) 52.65,42.72 52.31,42.38 U1.A6
  TOP w0.152: v1(44.2,69.04) v1(52.86,69.04)
  INTERNAL2 w0.127: v2(52.65,43.05) 52.88,43.05 53.11,43.28 v3(53.16,43.28)
  INTERNAL3 w0.127: v1(52.86,69.04) 53.31,68.58 53.31,44.47 53.16,44.32 v3(53.16,43.28)
  INTERNAL3 w0.152: CS_EN.1 v1(44.2,69.04)
  INTERNAL3 w0.254: v4(11.38,69.42) 11.38,79.5 9.98,80.9 v1(9.98,86.51)
  BOTTOM w0.254: v1(9.98,86.51) 9.27,86.51 9.25,86.49 5.31,86.49 5.23,86.56 J7.2 ; v4(11.38,69.42) 11.76,69.04 v1(44.2,69.04)
UNNAMED_1_EVQ-Q2XXXX_I7_1: length 70
  TOP w0.254: J8.1 17.81,59.84 ; 17.81,59.84 16.31,58.35 SW8.1 ; 17.81,59.84 17.83,59.87 19.09,59.87 19.11,59.89 19.66,59.89 21.23,61.47 R2.2 v1(27.28,62.94) ; v1(59,82.63) 59.38,82.63 59.61,82.86 59.61,83.25 Q1.3
  INTERNAL3 w0.254: v1(59,82.63) 59,78.46 59.39,78.08 v1(59.39,62.94)
  BOTTOM w0.254: v1(27.28,62.94) v1(59.39,62.94)
UNNAMED_1_EVQ-Q2XXXX_I149_1: length 105.1
  TOP w0.508: SW4.1 2,31.75 2.43,32.18 9.87,32.18 11.32,30.74 SW5.1 11.17,29.49 v1(10.04,29.49) ; SW6.1 2,18.97 2.74,19.71 9.59,19.71 11.32,17.99 ; 11.32,17.99 SW7.1 11.24,16.81 v1(10.04,16.81) ; 11.32,17.99 12.91,19.58 R23.1 ; v1(10.04,41.58) SW3.1 11.32,42.68 9.7,44.3 2.61,44.3 2,43.68 SW2.1 ; v1(10.04,53.87) SW1.1 11.32,52.77 9.55,51 2.75,51 2,51.76 SW0.1
  INTERNAL3 w0.508: v1(10.04,53.87) v1(10.04,41.58) v1(10.04,29.49) v1(10.04,16.81)
UNNAMED_1_HEADER2P_I176_1: length 6
  TOP w0.508: J5.1 55.5,94.03 55.52,94.01 55.52,92.62 54.87,91.97 DS2.1
UNNAMED_1_HEADER2PX3R_I166_2: length 17.6
  INTERNAL3 w0.254: R12.2 26.75,2.69 26.72,2.72 26.72,4.57 25.58,5.71 25.17,5.71 23.39,7.49 23.39,15.57 J3.2
UNNAMED_1_HEADER2PX3R_I166_4: length 10.6
  TOP w0.254: R1.2 29.26,8.36 RT1.1 29.26,11.89 28.65,12.5 28.65,15.65 J3.4
UNNAMED_1_HEADER2PX3R_I166_6: length 15.7
  TOP w0.254: R15.2 25.72,8.35 R13.1 v1(25.71,12.14)
  INTERNAL3 w0.254: v1(31.14,12.14) 31.14,15.7 J3.6
  BOTTOM w0.254: v1(25.71,12.14) v1(31.14,12.14)
UNNAMED_1_LED3P_I117_K: length 1.1
  TOP w0.762: R9.1 52.53,48.3
UNNAMED_1_RESSMD_I170_1: length 6.8
  TOP w0.254: R7.1 62.28,82.86 62.26,82.84 Q1.1 61.42,82.75 v1(61.42,81.94)
  INTERNAL3 w0.254: EN_EXT.1 v1(61.42,81.94)
UNNAMED_2_CAPNP_I23_1: length 5.9
  BOTTOM w0.381: R265.2 87.87,12.51 C227.1 86.78,12.53 R268.1 85,12.53 84.97,12.51 U207.3 83.83,11.74 83.82,11.73 R264.2
UNNAMED_2_CAPNP_I24_1: length 5.5
  BOTTOM w0.381: R263.2 80.92,11.73 80.93,11.74 U207.4 79.41,12.51 C225.1 78.32,12.38 R266.1 77.32,12.36 R267.1
UNNAMED_2_CAPNP_I24_2: length 70.9
  INTERNAL2 w0.381: v1(79.25,14.55) 79.99,15.28 v1(83.83,15.28)
  INTERNAL3 w0.254: v1(79.25,14.55) 80.62,15.92 80.62,72.18 80.59,72.2 v1(80.59,72.81)
  BOTTOM w0.254: R269.1 v1(80.59,72.81) ; v1(79.25,14.55) 79.25,13.63 C225.2 79.26,13.58 R266.2 78.29,13.6 R267.2
  BOTTOM w0.381: U207.1 v1(83.83,15.28)
UNNAMED_2_CAPNP_I84_2: length 4.5
  BOTTOM w0.254: C238.2 88.34,83.93 R282.1 88.22,82.84 R281.2 87.04,82.08 87.04,82.07 U209.12
UNNAMED_2_CAPNP_I88_2: length 3.3
  BOTTOM w0.254: R285.2 87.31,71.89 C249.2 87.31,73.49 87.04,73.75 U209.5
UNNAMED_2_CAPNP_I90_2: length 7.2
  BOTTOM w0.254: R301.1 86.33,68.9 C252.2 ; R301.1 87.19,69.84 R302.2 ; R301.1 86.29,69.88 86.29,71.05 86.31,71.07 86.31,73.72 86.41,73.83 U209.6
UNNAMED_2_EKCAPNP_I56_2: length 5.2
  BOTTOM w0.381: 94.29,72.59 94.42,72.71 C234.2 ; 94.29,72.59 R277.2 ; 94.29,72.59 95.93,72.59 U210.4 95.86,72.1 95.86,71.43 96.2,71.09 R280.1
UNNAMED_2_EKCAPNP_I61_2: length 2.9
  BOTTOM w0.381: U210.5 95.93,74.49 94.44,74.49 C235.2 94.42,75.56 R279.1
UNNAMED_2_EKCAPNP_I74_2: length 3.6
  BOTTOM w0.254: U209.16 89.58,81.36 90.53,82.3 90.53,82.94 C237.2 91.41,82.96 R286.2
UNNAMED_2_EKCAPNP_I107_2: length 2
  BOTTOM w0.254: C223.2 70.66,73.48 70.6,73.55 U205.1
UNNAMED_2_EKRESSMD_I63_2: length 2.3
  BOTTOM w0.381: U210.3 99.04,71.61 98.52,71.09 R280.2
UNNAMED_2_EKRESSMD_I79_2: length 8.4
  INTERNAL3 w0.203: v4(88.31,82.01) v4(88.31,87.96)
  BOTTOM w0.203: U209.14 v4(88.31,82.01) ; R303.2 88.29,87.99 v4(88.31,87.96)
UNNAMED_2_EKRESSMD_I80_2: length 6.8
  INTERNAL3 w0.203: v4(87.68,81.99) v4(87.68,87)
  BOTTOM w0.203: U209.13 v4(87.68,81.99) ; v4(87.68,87) R304.2
UNNAMED_2_EKRESSMD_I93_1: length 11
  BOTTOM w0.254: AIN1.1 92.41,68.83 91.43,69.81 R302.1
UNNAMED_2_EKRESSMD_I109_2: length 4.5
  BOTTOM w0.254: R307.2 66.55,78.94 67.35,79.75 U205.9
UNNAMED_2_EKRESSMD_I110_2: length 1.7
  BOTTOM w0.254: U205.12 69.31,80.96 69.31,82.62 R283.2
UNNAMED_2_EKRESSMD_I111_2: length 1.8
  BOTTOM w0.203: U205.10 68,82.69 R305.2
UNNAMED_2_EKRESSMD_I112_2: length 2.7
  BOTTOM w0.203: R306.2 68.19,83.41 68.64,82.96 68.64,82.51 68.65,82.51 U205.11
UNNAMED_2_EKRESSMD_I113_2: length 3.1
  BOTTOM w0.254: R308.2 66.31,79.96 66.7,80.35 U205.8
UNNAMED_2_EKRESSMD_I114_1: length 1.7
  BOTTOM w0.254: R214.1 70.61,82.57 70.6,82.56 U205.14
UNNAMED_2_MAX14689_I1_COM1: length 2.6
  TOP w0.127: v1(80.93,8.36) 81.29,8.36 81.68,7.97 U206.B1
  BOTTOM w0.127: R263.1 80.92,8.91 80.93,8.91 v1(80.93,8.36)
UNNAMED_2_MAX14689_I1_COM2: length 2.6
  TOP w0.127: v1(83.8,8.37) 83.4,7.97 U206.B3
  BOTTOM w0.127: v1(83.8,8.37) 83.8,9.26 83.82,9.27 R264.1
UNNAMED_2_MAX14689_I1_NC1: length 7.4
  TOP w0.127: U206.C3 82.76,7.57 v1(82.76,7.05)
  TOP w0.152: U206.A1 v1(81.61,8.72)
  BOTTOM w0.127: R261.2 79.47,7.57 79.59,7.7 80.38,7.7 81.03,7.05 v1(82.76,7.05)
  BOTTOM w0.152: v1(82.76,7.05) 82.76,7.62 82.05,8.33 82,8.33 v1(81.61,8.72)
UNNAMED_2_RESSMD_I81_1: length 9.4
  TOP w0.381: v1(93.09,85.14) AIN7.1
  BOTTOM w0.381: R281.1 87.04,84.15 88.03,85.14 v1(93.09,85.14)
UNNAMED_2_RESSMD_I95_2: length 5.1
  BOTTOM w0.254: Q206.3 94.93,80.57 94.94,80.57 Q205.1 93.76,82.39 93.53,82.15 93.31,82.15 R288.2
UNNAMED_4_24AA02_I200_SCL: length 2.3
  TOP w0.254: U108.1 48.01,82.43 47.97,82.47 R162.2
UNNAMED_4_24AA02_I200_SDA: length 2
  TOP w0.254: R164.1 48.22,80.54 48.23,80.53 U108.3
UNNAMED_4_24AA02_I200_VCC: length 7.9
  TOP w0.254: U108.4 53.59,80.53 53.6,80.55 C14.2 54.64,80.58 55.58,80.58 R163.1 56.23,80.55 56.24,80.54 56.52,80.54 56.9,80.92 56.9,82.19 56,83.09 R165.1
UNNAMED_4_24AA02_I200_WP: length 2.5
  TOP w0.254: U108.5 54.05,82.43 R166.1 54.21,83.09 R165.2
UNNAMED_4_10103592-0001LF_I212_1: length 8.4
  TOP w0.254: J6.1 5.49,73.22 5.49,73.22
  TOP w0.381: 5.49,73.22 7.28,73.22 7.61,72.9 FB100.1 9.54,72.9 9.84,73.2 C155.1
UNNAMED_4_10103592-0001LF_I212_2: length 7.2
  TOP w0.254: R123.1 11.77,74.37 11.27,73.87 5.79,73.87 5.79,73.87 J6.2
UNNAMED_4_10103592-0001LF_I212_3: length 7.2
  TOP w0.254: J6.3 5.86,74.52 5.87,74.52 11.11,74.52 11.77,75.18 R103.1
UNNAMED_4_10103592-0001LF_I212_SHIELD10: length 20.4
  TOP w0.254: J6.6 2.39,78.55 2.39,78.54 ; J6.9 2.57,70.42 ; 2.37,75.41 2.32,75.46 J6.11 ; J6.8 5.65,72.1 5.65,72.1 ; 2.37,73.58 2.37,73.59 J6.10 ; J6.7 5.65,76.95 5.65,76.95
  TOP w0.508: 5.65,76.95 4.24,76.95 2.65,78.54 2.39,78.54 2.37,78.52 2.37,70.62 2.57,70.42 4.24,72.1 5.65,72.1
  TOP w0.635: R142.1 8.07,78.54 R122.1 6.91,77.44 6.89,77.42 6.12,77.42 5.65,76.95
UNNAMED_4_CAPNP_I101_2: length 6.8
  TOP w0.254: Y101.3 26.21,91.44 C153.2 26.21,89.87 25.95,89.62 U100.41
UNNAMED_4_CAPNP_I105_2: length 6.1
  TOP w0.254: U100.42 22.08,90.12 22.58,90.62 22.58,92.63 22.83,92.89 23.45,92.89 C152.2 23.94,92.98 Y101.1
UNNAMED_4_EKCAPNP_I12_1: length 16.9
  TOP w0.254: U101.16 15.79,73.18 C156.2 14.33,73.22 14.33,73.53 14.15,73.71 v1(14.12,73.71) ; v1(20.55,79.89) 20.33,79.67 C159.1 20.07,79.1 20.07,78.53 20.06,78.52 U101.1
  INTERNAL3 w0.254: v1(14.12,73.71) 14.55,74.14 14.55,74.37 14.91,74.73 v1(14.91,79.89)
  BOTTOM w0.254: v1(20.55,79.89) v1(14.91,79.89)
UNNAMED_4_EKCAPNP_I29_1: length 1.4
  TOP w0.635: R142.2 C114.1
UNNAMED_4_EKRESSMD_I15_2: length 2.8
  TOP w0.254: U101.15 14.76,73.71 14.58,73.89 14.58,73.9 14.31,74.17 14.3,74.17 14.1,74.37 R123.2
UNNAMED_4_EKRESSMD_I16_2: length 3
  TOP w0.254: R103.2 13.89,75.18 14.87,74.21 U101.14
UNNAMED_4_EKRESSMD_I17_1: length 1.7
  TOP w0.254: U101.22 19.06,71.57 18.99,71.5 R111.1
UNNAMED_4_EKRESSMD_I17_2: length 2.2
  TOP w0.254: D100.K 20.14,70.26 19.81,69.92 R111.2
UNNAMED_4_EKRESSMD_I18_1: length 1.8
  TOP w0.254: U101.21 18.56,71.24 R109.1
UNNAMED_4_EKRESSMD_I18_2: length 4
  TOP w0.254: R109.2 18.15,69.35 18.33,69.16 19.12,69.16 20.14,68.15 D101.K
UNNAMED_4_EKRESSMD_I87_1: length 2.5
  TOP w0.254: U107.3 26.66,78.55 26.2,78.09 R150.1
UNNAMED_4_EKRESSMD_I109_1: length 3.2
  TOP w0.254: U100.36 24.02,87.12 24.28,86.85 R155.1
UNNAMED_4_EKRESSMD_I113_1: length 3.1
  TOP w0.254: R148.1 24.3,87.67 24.25,87.62 U100.37
UNNAMED_4_EKRESSMD_I149_1: length 2.6
  TOP w0.254: R138.1 35.09,45.67 Q100.1 34.5,46.93 34.5,46.92 R141.1
UNNAMED_4_EKRESSMD_I150_1: length 2.8
  TOP w0.254: R139.1 39.55,47.89 Q101.1 39.68,46.56 R137.1
UNNAMED_4_EKRESSMD_I151_2: length 26.1
  TOP w0.152: R141.2 33.71,47.75 v1(32.94,47.75)
  INTERNAL3 w0.152: QSDA.1 32.92,71.79 32.83,71.7 32.83,48.43 32.94,48.31 v1(32.94,47.75)
UNNAMED_4_EKRESSMD_I152_2: length 24.2
  TOP w0.152: R139.2 38.65,48.8 v1(38.65,49.25)
  INTERNAL3 w0.152: QSCL.1 38.71,66.1 38.65,66.04 v1(38.65,49.25)
UNNAMED_4_EKRESSMD_I153_1: length 1.8
  TOP w0.254: R135.1 25.6,80.57 25.73,80.71 U107.1
UNNAMED_4_EKRESSMD_I154_1: length 1.8
  TOP w0.254: R136.1 25.48,79.82 25.56,79.91 U107.2
UNNAMED_4_EKRESSMD_I171_2: length 1.6
  TOP w0.254: R143.2 29.38,76.97 29.36,76.99 U107.6
UNNAMED_4_EKRESSMD_I174_1: length 3.9
  TOP w0.254: R156.2 45.31,91.2 R157.1 45.73,91.25 46.09,90.89 46.09,89.98 45.44,89.33 U104.4
UNNAMED_4_EKRESSMD_I177_1: length 1.7
  TOP w0.254: R158.2 33.87,89.01 R159.1 33.86,88.99 U102.4
UNNAMED_4_EKRESSMD_I190_2: length 2.7
  TOP w0.254: U107.8 31.55,79.91 31.59,79.94 R151.2 32.17,80.85 R152.2
UNNAMED_4_LED_I7_B: length 2.4
  TOP w0.254: R110.1 27.59,88.47 28.39,87.67 D102.K
UNNAMED_4_LED_I189_B: length 1.8
  TOP w0.254: R151.1 33.9,79.94 33.93,79.92 D103.K
UNNAMED_4_MAX3395E_I94_I: length 5.5
  TOP w0.254: U107.4 27.76,77.63 v1(27.18,77.05)
  INTERNAL3 w0.254: v1(27.18,77.05) 27.18,73.56 I/OVL4.1
UNNAMED_4_MAX3395E_I94_I_1: length 5.7
  TOP w0.254: I/OVCC4.1 34.85,78.18 33.92,79.11 U107.7
UNNAMED_4_MAX8512_I5_FB: length 2
  TOP w0.254: R160.2 R161.1 40.02,89.04 U103.4
UNNAMED_6_CAPNP_I21_1: length 28.1
  INTERNAL3 w0.254: v4(63.36,47.73) 63.36,48.52 63.5,48.66 v4(63.5,52.17) ; v4(74.7,52.17) v4(74.7,45.09)
  BOTTOM w0.254: R202.2 v4(63.36,47.73) ; 74.66,45.79 75.63,45.79 R205.1 ; 74.66,45.79 74.66,45.13 v4(74.7,45.09) ; 74.66,45.79 C203.1 74.69,45.78 74.44,46.02 74.24,46.02 73.99,46.27 73.99,46.56 73.64,46.91 U200.7 ; v4(63.5,52.17) 74.09,52.17 74.09,52.17 v4(74.7,52.17)
UNNAMED_6_CAPNP_I271_2: length 16
  BOTTOM w0.127: R229.1 81.98,42.82 78.02,38.86 74.52,38.86 73.3,37.64 U201.5
  BOTTOM w0.152: 75.26,38.86 75.24,38.88 R295.1
  BOTTOM w0.254: U201.5 72.18,38.24 72.19,38.25 C208.2 72.19,40.27 R226.2
UNNAMED_6_CAPNP_I277_1: length 20.6
  INTERNAL3 w0.254: v4(63.88,33.35) 63.88,36.58 v4(63.25,37.21) ; v4(74.17,34.82) v4(74.17,33.35)
  BOTTOM w0.254: v4(74.17,33.35) v4(63.88,33.35) ; v4(63.25,37.21) 63.77,37.21 R223.2 ; U201.7 73.37,36.34 74.08,35.62 R228.1 ; C209.1 74.18,35.64 R228.1 ; R228.1 v4(74.17,34.82)
UNNAMED_6_CAPNP_I277_2: length 15.2
  BOTTOM w0.127: R230.1 81.71,42.03 78.21,38.52 74.57,38.52 73.38,37.33 73.38,37 73.38,37
  BOTTOM w0.152: R296.2 75.26,38.5 75.23,38.52
  BOTTOM w0.254: C209.2 75.17,36.84 R228.2 74.02,36.99 73.36,36.99 ; 73.36,36.99 U201.6 ; 73.36,36.99 73.38,37
UNNAMED_6_CAPNP_I289_2: length 3.2
  BOTTOM w0.254: U201.3 65.84,36.99 65.67,37.16 C248.2 65.58,37.24 65.25,37.57 65.25,37.6 64.94,37.91 R224.2
UNNAMED_6_CAPNP_I307_2: length 15.9
  BOTTOM w0.127: 72.82,29.56 73.79,29.56 75.03,30.81 77.97,30.81 82.06,34.9 82.41,34.9 82.83,35.33 R242.1
  BOTTOM w0.152: 75.39,30.81 75.4,30.82 R297.1
  BOTTOM w0.254: R240.2 72.23,30.89 C214.2 72.22,30.2 72.24,30.17 U202.5 72.82,29.56
UNNAMED_6_CAPNP_I311_1: length 24.1
  INTERNAL3 w0.254: v1(63.75,29.71) v1(63.75,24.71) ; v1(75.08,24.71) v1(75.08,26.92)
  BOTTOM w0.254: R236.2 63.72,29.67 v1(63.75,29.71) ; v1(63.75,24.71) v1(75.08,24.71) ; C213.1 75.98,27.74 R239.1 ; C213.1 75.08,27.57 v1(75.08,26.92) ; C213.1 74.24,27.74 74.17,27.74 73.64,28.26 U202.7
UNNAMED_6_CAPNP_I311_2: length 15.9
  BOTTOM w0.127: R243.1 82.17,34.5 78.09,30.43 75.13,30.43 73.62,28.91
  BOTTOM w0.152: 75.39,30.43 75.38,30.42 R298.2
  BOTTOM w0.254: C213.2 74.95,28.92 74.95,28.91 ; U202.6 74.95,28.91 ; 74.95,28.91 74.96,28.91 74.99,28.94 R239.2
UNNAMED_6_CAPNP_I323_2: length 3.3
  BOTTOM w0.254: R237.2 64.67,29.69 65.1,29.69 65.3,29.49 65.3,29.49 65.37,29.41 65.38,29.41 65.63,29.16 C250.2 66.39,29.16 66.63,28.91 U202.3
UNNAMED_6_CAPNP_I341_2: length 16.8
  BOTTOM w0.127: R254.1 82.02,63.57 79.57,66.01 74.94,66.01 73.28,64.36 U203.5
  BOTTOM w0.152: 74.48,65.55 74.36,65.67 R299.1
  BOTTOM w0.254: U203.5 72.17,65.28 72.23,65.34 C218.2 72.23,67.21 R252.2
UNNAMED_6_CAPNP_I345_1: length 23.4
  INTERNAL3 w0.254: v4(63.67,64.8) v4(63.67,59.19) ; v4(74.32,59.24) v4(74.32,61.11)
  BOTTOM w0.254: v4(74.32,61.11) 74.32,61.7 C219.1 ; C219.1 74.22,61.72 72.88,63.06 U203.7 ; C219.1 75.34,61.72 R253.1 ; R249.2 v4(63.67,64.8) ; v4(74.32,59.24) 73.71,59.24 73.66,59.19 v4(63.67,59.19)
UNNAMED_6_CAPNP_I345_2: length 16.1
  BOTTOM w0.127: 73.6,63.78 73.6,64.26 75.06,65.71 79.42,65.71 82.43,62.7 R255.1
  BOTTOM w0.152: R300.2 74.36,64.66 74.18,64.83
  BOTTOM w0.254: R253.2 75.34,62.94 C219.2 74.31,62.94 73.54,63.71 ; 73.6,63.78 73.54,63.71 ; 73.54,63.71 U203.6
UNNAMED_6_CAPNP_I357_2: length 3.5
  BOTTOM w0.254: U203.3 65.82,63.71 65.67,63.87 65.67,64.05 65.63,64.08 C251.2 65.58,64.21 65.44,64.21 65.41,64.24 65.32,64.24 65.25,64.31 65.25,64.4 65.06,64.58 R250.2
UNNAMED_6_CAPNP_I359_2: length 3.2
  BOTTOM w0.254: R203.2 65.06,48.45 65.58,47.93 C200.2 66.03,47.56 U200.3
UNNAMED_6_EKCAPNP_I10_1: length 3.8
  BOTTOM w0.254: R202.1 64.7,47.72 C201.1 64.72,46.8 65.63,46.8 65.75,46.91 U200.2
UNNAMED_6_EKCAPNP_I10_2: length 1.2
  BOTTOM w0.254: R201.1 63.8,45.68 C201.2
UNNAMED_6_EKCAPNP_I237_2: length 1.9
  TOP w0.381: v1(91.36,48.56) 91.25,48.67 C239.2
  BOTTOM w0.254: v1(91.36,48.56) 91.18,48.56 91.08,48.47 R212.1
  BOTTOM w0.381: v1(91.36,48.56) 91.83,48.56 Q200.8
UNNAMED_6_EKCAPNP_I261_2: length 2.3
  TOP w0.254: C240.2 v1(91.53,40.93)
  BOTTOM w0.254: R227.1 91.12,40.7 91.24,40.82 91.42,40.82 v1(91.53,40.93)
  BOTTOM w0.381: v1(91.53,40.93) 92.07,40.93 Q201.8
UNNAMED_6_EKCAPNP_I287_1: length 4
  BOTTOM w0.254: U201.2 65.92,36.34 65.66,36.08 64.73,36.08 C206.1 64.73,37.16 R223.1
UNNAMED_6_EKCAPNP_I287_2: length 1.2
  BOTTOM w0.254: C206.2 63.83,36.07 R222.1
UNNAMED_6_EKCAPNP_I298_2: length 1.9
  TOP w0.381: v1(91.49,33.5) 91.43,33.56 C241.2
  BOTTOM w0.254: R246.1 90.95,33.56 91.43,33.56 v1(91.49,33.5)
  BOTTOM w0.381: v1(91.49,33.5) 91.97,33.5 Q202.8
UNNAMED_6_EKCAPNP_I321_1: length 4.1
  BOTTOM w0.254: U202.2 65.5,28.26 65.2,27.97 C211.1 64.62,29 R236.1
UNNAMED_6_EKCAPNP_I321_2: length 1.1
  BOTTOM w0.254: C211.2 63.72,26.9 R235.1
UNNAMED_6_EKCAPNP_I332_2: length 2.5
  TOP w0.381: C242.2 91.01,61.39 v1(91.45,61.39)
  BOTTOM w0.254: v1(91.45,61.39) 91.16,61.39 90.96,61.19 90.83,61.19 R259.1
  BOTTOM w0.381: Q203.8 92.02,61.39 v1(91.45,61.39)
UNNAMED_6_EKCAPNP_I355_1: length 4
  BOTTOM w0.254: U203.2 65.83,63.06 65.68,62.91 64.62,62.91 C216.1 64.59,63.91 R249.1
UNNAMED_6_EKCAPNP_I355_2: length 1.2
  BOTTOM w0.254: R248.1 63.69,61.78 C216.2
UNNAMED_6_EKRESSMD_I42_1: length 15.5
  BOTTOM w0.127: 74.85,48.68 80.76,48.68 82.01,49.93 R207.1 ; 74.85,48.68 73.81,48.68 73.34,48.21 U200.5 ; 74.85,48.68 74.85,48.68 R293.1
  BOTTOM w0.254: 72.27,50.85 R206.2 ; 72.27,50.85 C204.2 ; 72.27,50.85 72.28,50.84 72.28,49.1 72.22,49.05 U200.5
UNNAMED_6_EKRESSMD_I42_2: length 12
  BOTTOM w0.127: R211.1 90.19,51.58 90.19,51.04 90.1,50.95 89.3,50.95 87.75,49.4 84.6,49.4 84.08,49.93 R207.2
  BOTTOM w0.762: VIL_SBB0.1 86.87,50.61 86.78,50.7
  BOTTOM w0.889: 86.78,50.7 87.67,51.59 R211.1
UNNAMED_6_EKRESSMD_I43_1: length 14.4
  BOTTOM w0.127: 74.8,48.36 73.89,48.36 73.46,47.93 73.46,47.59 73.48,47.56 ; 74.8,48.36 81.05,48.36 81.83,49.14 R208.1 ; 74.8,48.36 74.81,48.36 R294.2
  BOTTOM w0.254: R205.2 75.53,47.11 74.81,47.11 C203.2 74.33,46.98 73.76,47.55 73.5,47.55 73.48,47.56 U200.6
UNNAMED_6_EKRESSMD_I99_1: length 4.2
  BOTTOM w0.254: 65.63,45.58 65.72,45.58 66.05,45.91 66.05,45.99 66.32,46.26 U200.1 ; 65.63,45.58 65.55,45.67 R201.2 ; 65.63,45.58 65.51,45.46 R204.1
UNNAMED_6_EKRESSMD_I99_2: length 50.6
  INTERNAL3 w0.254: J200.1 97.03,52.53 v1(97.03,55.83) ; v4(64,44.6) 64,45.21 64.03,45.24 v4(64.03,55.83)
  BOTTOM w0.254: R204.2 v4(64,44.6) ; v1(97.03,55.83) 64.72,55.83 64.71,55.83 v4(64.03,55.83)
UNNAMED_6_EKRESSMD_I273_2: length 11.7
  BOTTOM w0.127: R229.2 84.09,42.82 85.35,41.55 88.19,41.55 89.31,42.68 90.08,42.68 90.16,42.76 R233.1
  BOTTOM w0.889: R233.1 88.86,43.33 88.35,42.81 VIL_SBB1.1
UNNAMED_6_EKRESSMD_I278_1: length 4.4
  BOTTOM w0.254: R225.1 64.71,34.89 R222.2 65.61,34.91 65.66,34.86 67.26,34.86 67.48,35.08 U201.1
UNNAMED_6_EKRESSMD_I278_2: length 61.8
  INTERNAL3 w0.254: J202.1 98.67,41.28 97.52,40.14 97.34,40.14 95.45,38.25 v4(95.45,24.06) ; v4(63.13,34.01) v4(63.13,24.06)
  BOTTOM w0.254: v4(63.13,24.06) v4(95.45,24.06) ; R225.2 v4(63.13,34.01)
UNNAMED_6_EKRESSMD_I306_2: length 12.1
  BOTTOM w0.127: R242.2 84.26,35.38 85.29,34.34 88.37,34.34 89.78,35.74 90.32,35.74 90.42,35.84 90.42,36.38 R245.1
  BOTTOM w0.889: VIL_SBB2.1 88.1,36.41 R245.1
UNNAMED_6_EKRESSMD_I313_1: length 4.1
  BOTTOM w0.254: R238.1 64.6,26.77 R235.2 65.37,26.84 66.15,27.61 U202.1
UNNAMED_6_EKRESSMD_I313_2: length 38.9
  BOTTOM w0.254: J204.1 98.81,30.37 93.77,25.33 64.02,25.33 63.7,25.65 R238.2
UNNAMED_6_EKRESSMD_I340_2: length 10.5
  BOTTOM w0.127: R254.2 84.61,63.57 85.1,63.07 88.09,63.07 88.72,63.7 89.9,63.7 90.05,63.85 R258.1
  BOTTOM w0.889: VIL_LDO.1 88.62,64.74 88.97,64.4 R258.1
UNNAMED_6_EKRESSMD_I347_1: length 4.2
  BOTTOM w0.254: R251.1 64.58,60.78 R248.2 65.56,61.77 66.19,62.41 U203.1
UNNAMED_6_EKRESSMD_I347_2: length 46.3
  INTERNAL3 w0.254: v4(98.86,56.57) 98.86,57.18 98.86,57.18 98.86,60.85 98.86,60.86 98.86,61.72 98.81,61.77 J206.1 ; v4(63.03,60.72) 63.03,57.19 63.02,57.18 v4(63.02,56.57)
  BOTTOM w0.254: R251.2 v4(63.03,60.72) ; v4(98.86,56.57) v4(63.02,56.57)
UNNAMED_6_HEADER2P_I444_2: length 5.2
  BOTTOM w0.254: J202.2 98.38,43.82 98.35,43.85 97.56,43.85 97.02,44.39 R231.2 95.36,44.39 95.35,44.4 95.07,44.4 94.64,43.97 Q201.4
UNNAMED_6_HEADER2P_I446_2: length 7.2
  INTERNAL3 w0.254: J204.2 98.81,35.42 98.81,35.42
  INTERNAL3 w0.381: v1(98.75,36.66) 98.75,35.98 98.81,35.93 98.81,35.42
  BOTTOM w0.508: Q202.4 96.86,36.76 96.96,36.66 R244.2 v1(98.75,36.66)
UNNAMED_6_HEADER2P_I448_2: length 4.8
  BOTTOM w0.254: J206.2 98.83,64.66 98.87,64.7 97.61,64.7 97.54,64.77 R257.2 95.17,64.77 95.12,64.72 Q203.4
UNNAMED_6_MAX44251_I450_INA: length 3.7
  BOTTOM w0.254: R272.1 75.79,72.8 R271.2 75.76,73.45 75.49,73.72 U204.3
UNNAMED_6_MAX44251_I451_INB: length 3.1
  BOTTOM w0.254: R273.2 73.86,80.19 73.87,80.2 U204.5
  BOTTOM w0.381: R273.2 R274.1
UNNAMED_6_RESSMD_I28_2: length 7.1
  BOTTOM w0.254: Q200.4 93.93,52.77 93.93,52.77 R210.2 94.69,53.8 95.17,53.31 J200.2
UNNAMED_7_EVKITINDUCT_I24_1: length 12.5
  TOP w0.381: L2.1 99.32,12.85 99.39,12.91 99.39,14.26 99.44,14.31 L3.1 99.44,16.57 99.33,16.69 L4.1 99.33,21.16 99.41,21.25 L5.1
UNNAMED_7_EVKITINDUCT_I24_2: length 12.6
  TOP w0.381: L5.2 97.38,22.86 97.73,22.52 L4.2 97.73,18.67 97.86,18.53 L3.2 97.86,14.31 97.98,14.19 L2.2
VADC: length 15.5
  INTERNAL3 w0.508: v4(92.35,82.17) 91.7,81.52 v1(91.7,72.56)
  BOTTOM w0.254: Q205.2 93.76,84.29 93.22,83.76 R288.1 93.22,82.96 R286.1
  BOTTOM w0.381: v4(92.35,82.17) 92.35,82.93 R286.1
  BOTTOM w0.508: R277.1 v1(91.7,72.56)
VIO: length 126.2
  TOP w0.254: R107.1 v1(25.55,79) ; R10.2 52.4,75.43 52.38,75.46 R17.2 47.26,75.46 35.38,75.46 ; R14.2 25.5,75.44 v1(25.55,75.39) 28.65,75.39 28.74,75.49 R143.1 30.01,75.49 30.04,75.46 35.38,75.46 ; C120.2 27.03,82.91 27.76,82.18 U107.12 25.99,81.81 v1(25.55,81.36) 24.96,81.36 R108.1 ; 35.38,75.46 35.36,75.49 v1(35.03,75.49)
  INTERNAL3 w0.254: v1(25.55,81.36) v1(25.55,79) v1(25.55,75.39) ; v1(36.32,91.52) 35.43,91.52 35.03,91.11 v1(35.03,75.49) ; v1(8.36,88.85) 8.36,88.24 8.38,88.21 8.38,83.11 8.41,83.08 v1(8.41,80.87)
  BOTTOM w0.254: v1(25.55,81.36) 22.38,81.36 21.97,80.95 9.1,80.95 9.02,80.87 v1(8.41,80.87) ; v1(8.36,88.85) 6.31,88.85 6.13,89.03 5.36,89.03 5.28,89.1 J7.1
  BOTTOM w0.381: v1(36.32,91.52) 37.24,92.43 63.6,92.43 J101.5 J101.3 J101.1 73.76,93.93 73.86,93.83 J2.1
VL: length 71.2
  TOP w0.203: U1.D1 50.07,41.05
  TOP w0.254: v1(46.66,40.79) 46.23,40.36 22,40.36 21.64,40.01 v1(21.03,40.01) ; v2(48.63,41.25) 49.34,41.25 49.54,41.05 50.07,41.05 ; VL.1 16.92,6.5 v1(21.03,6.5)
  INTERNAL2 w0.254: v2(48.63,41.25) v3(48.29,41.25)
  INTERNAL3 w0.254: v1(46.66,40.79) 47.12,41.25 v3(48.29,41.25) ; v1(21.03,40.01) v1(21.03,6.5)
VLDO: length 41
  INTERNAL3 w0.152: v4(88.68,61.04) 88.68,69.36 86.41,71.63 v4(86.41,77.85)
  INTERNAL3 w0.254: v4(79.2,77.85) v4(79.2,84.05)
  BOTTOM w0.254: C220.2 73.61,83.21 ; 73.61,83.21 73.61,83.79 73.86,84.05 v4(79.2,84.05) ; 73.61,83.21 73.62,83.2 R260.1 73.61,82.06 73.61,81.48 R273.1 ; v4(88.68,61.04) 89.78,61.04 R259.2 ; v4(86.41,77.85) v4(79.2,77.85)
VSBB0: length 42.6
  INTERNAL3 w0.254: v1(73.46,69.22) 73.46,72.54 73.71,72.8 v1(73.71,73.41) ; v4(89.19,48.47) v4(89.19,66.91)
  BOTTOM w0.254: v4(89.19,66.91) 83.52,66.91 83.52,66.9 80.98,66.9 78.66,69.22 v1(73.46,69.22) ; R212.2 89.71,48.49 89.21,48.49 v4(89.19,48.47) ; R213.1 73.73,73.11 73.71,73.13 v1(73.71,73.41) ; R213.1 73.66,72.78 C205.2 ; R213.1 73.75,72.82 R271.1
VSBB1: length 47.5
  INTERNAL3 w0.254: v4(84.32,80.68) 84.32,62.31 85.01,61.62 v4(85.01,40.81)
  BOTTOM w0.152: v4(85.01,40.81) 85.56,40.81 85.73,40.97 88.03,40.97 88.31,40.7 R227.2
  BOTTOM w0.254: C210.2 83.58,79.83 R234.1 83.59,80.68 v4(84.32,80.68) U209.9
VSBB2: length 56.1
  INTERNAL3 w0.152: v4(88.39,32.87) 88.39,33.42 88.19,33.62 88.19,61.21 88.24,69.19 85.77,71.66 v1(85.77,82.45)
  BOTTOM w0.254: v4(88.39,32.87) 89.02,33.5 R246.2 ; C215.2 84.97,82.48 R247.1 85.76,82.46 v1(85.77,82.45) U209.10
VSYS: length 101.2
  TOP w0.254: R16.1 28.6,54.64 ; R19.1 28.52,59.23 ; U1.E2 50.71,40.42 50.05,39.77 C11.1 50.07,39.25
  TOP w0.381: R20.2 v1(29.62,33.02) ; R22.2 v1(29.62,27.91) ; v1(49.23,38.84) 49.25,38.84 49.43,39.01 49.43,39.12 49.56,39.25 C11.1 ; R18.2 v1(29.62,37.67) ; R8.2 v1(29.54,45.42) ; R21.1 v1(29.62,63.86) ; R2.1 v1(29.67,61.47) ; 28.52,59.23 v1(29.62,59.23) ; R6.1 v1(29.57,50.11) ; v1(29.44,66.24) 20.37,66.24 19.33,67.28 2.82,67.28 1.2,65.67 SW9.1 ; 28.6,54.64 v1(29.59,54.64)
  INTERNAL3 w0.254: 29.62,45.57 29.54,45.49 v1(29.54,45.42) ; 29.62,61.21 29.67,61.26 v1(29.67,61.47) ; 29.62,54.38 29.59,54.41 v1(29.59,54.64) ; 29.62,50.22 29.57,50.16 v1(29.57,50.11)
  INTERNAL3 w0.381: v1(49.3,39.34) 49.33,39.32 49.33,38.94 v1(49.23,38.84) ; v1(29.62,63.86) 29.62,64.53 29.44,64.71 v1(29.44,66.24)
  INTERNAL3 w0.508: v1(29.62,27.91) v1(29.62,33.02) v1(29.62,37.67) v1(29.62,59.23) v1(29.62,63.86)
  BOTTOM w0.508: 47.02,51.38 30.84,51.38 v1(29.57,50.11)
  vias: v1(47.96,48.08) v1(47.96,47.4) v1(48.82,48.08) v1(48.82,47.4)
VUSB: length 339.1
  TOP w0.152: C224.1 82.23,6.44 82.23,7.26 82.36,7.4 U206.C2
  TOP w0.254: R115.1 8.41,69.29 C154.2 8.41,71.07 8.67,71.32 FB100.2 11.23,71.32 11.33,71.42 17.1,71.42 17.17,71.36 ; 17.17,71.36 17.23,71.29 C108.2 ; 17.17,71.36 17.17,71.55 17.56,71.94 U101.19 ; C118.2 31.62,85.12 U102.1 31.57,86.64 31.57,87.48 31.75,87.66 32.61,87.66 32.92,87.35 U102.3 ; C110.2 37.56,85.22 U103.1 37.52,86.69 37.52,87.57 37.77,87.83 38.6,87.83 38.86,87.57 U103.3 ; U104.3 45.44,87.43 45.21,87.66 44.27,87.66 44.09,87.48 44.09,86.64 U104.1 44.18,86.56 C112.2
  TOP w0.381: 43.81,84.09 44.18,84.46 C112.2 ; C118.2 31.57,85 v1(31.57,84.09) ; v1(8.36,68.45) 8.36,68.46 R115.1 ; C110.2 37.54,84.24 37.69,84.09 ; C224.1 v1(77.51,6.29)
  TOP w0.508: 33.88,84.09 v1(31.57,84.09) ; 33.88,84.09 v1(48.33,84.09) ; 33.88,84.09 33.9,84.07 v1(34.06,84.07) ; v1(34.75,17.48) v1(71.65,17.48)
  INTERNAL3 w0.381: v1(76.79,81.5) v1(76.79,85.51)
  INTERNAL3 w0.508: v1(31.57,84.09) v1(31.57,67.97) ; v1(77.51,6.29) v1(77.51,15.58) ; v1(71.65,17.48) 71.65,18.21 71.66,18.22 v4(71.66,26.44) v4(71.66,34.47) v4(71.66,45.16) 71.66,60.11 71.65,60.12 v4(71.65,60.86) ; v1(34.75,17.48) 34.79,17.48 ; v1(34.06,84.07) 34.06,85.95 32.59,87.43 32.59,89.66 32.08,90.17 32.08,90.4 31.83,90.65 31.83,92.66 J100.1 ; v1(96.8,83.11) 95.55,84.35 v1(95.55,86.03)
  INTERNAL3 w1.27: v4(34.85,68) 34.85,17.53 34.79,17.48 34.79,13.33 35.31,12.81 35.31,11.05 35.33,11.02 J4.2
  BOTTOM w0.254: U204.8 v1(76.79,81.5) 76.83,81.53 C229.1 ; U207.5 U207.6 80.93,15.53 C226.1 ; U203.8 72.17,61.39 72.35,61.21 C217.1 72.32,60.86 v4(71.65,60.86) ; v4(71.66,34.47) 71.76,34.57 C207.1 72.18,34.58 U201.8 ; U200.8 72.22,45.23 C202.1 71.72,45.22 v4(71.66,45.16) ; v4(71.66,26.44) C212.1 72.23,26.48 72.23,27.61 U202.8
  BOTTOM w0.381: Q206.1 97.14,80.07 98.84,80.07 R287.1 ; v1(77.51,15.58) 78.18,15.58 78.21,15.55 C226.1 ; 76.58,85.55 76.62,85.51 v1(76.79,85.51)
  BOTTOM w0.508: Q206.1 97.13,80.92 97.19,80.98 97.19,83.28 Q205.3 97.03,83.34 v1(96.8,83.11) ; v1(31.57,67.97) 31.79,67.97 31.8,67.98 ; v1(95.55,86.03) 86.97,86.03 86.49,85.55 49.78,85.55 v1(48.33,84.09) ; v1(77.51,15.58) 73.48,15.58 72.17,16.88 72.17,16.95 v1(71.65,17.48)
  BOTTOM w1.016: v4(34.85,68) 33.86,68 33.84,67.98 9.82,67.98 9.35,68.45 v1(8.36,68.45)
